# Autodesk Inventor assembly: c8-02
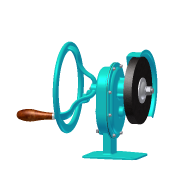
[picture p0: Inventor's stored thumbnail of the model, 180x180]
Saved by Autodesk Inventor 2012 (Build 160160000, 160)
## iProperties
Created: 2010-12
Part Number: c8-02
Document SubType Name: Assembly
Designer: Thom Tremblay
Author: Thom Tremblay
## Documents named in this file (27)
- C:\Users\VMuser\Desktop\Inventor 2012 Essentials\Assemblies\Chapter 8\c8-02.iam
- C:\Users\VMuser\Desktop\Inventor 2012 Essentials\Content Center Files\en-US\ANSI B93.98M\ANSI_B93.98M - 15x35x7-Type 2.ipt
- C:\Users\VMuser\Desktop\Inventor 2012 Essentials\Content Center Files\en-US\SKF B - angular contact\SKF B7202 BE.ipt
- C:\Users\VMuser\Desktop\Inventor 2012 Essentials\Content Center Files\en-US\IS 7483\IS 7483 - M4 x 8.ipt
- C:\Users\VMuser\Desktop\Inventor 2012 Essentials\Content Center Files\en-US\ISO 2795  F\ISO 2795 - 10 x 14 x 10F.ipt
- C:\Users\VMuser\Desktop\Inventor 2012 Essentials\Content Center Files\en-US\STN 022930\STN 022930 - 10.ipt
- C:\Users\VMuser\Desktop\Inventor 2012 Essentials\Content Center Files\en-US\STN 022930\STN 022930 - 15.ipt
- C:\Users\VMuser\Desktop\Inventor 2012 Essentials\Content Center Files\en-US\DIN 128\DIN 128 - A12.ipt
- C:\Users\VMuser\Desktop\Inventor 2012 Essentials\Content Center Files\en-US\ISO 4032\ISO 4032 - M12ISO.ipt
- C:\Users\VMuser\Desktop\Inventor 2012 Essentials\Content Center Files\en-US\ISO 4145 T8\ISO 4145 Plug T8 1_8.ipt
- C:\Users\VMuser\Desktop\Inventor 2012 Essentials\Parts\Chapter 8\c8-01.ipt
- C:\Users\VMuser\Desktop\Inventor 2012 Essentials\Parts\Chapter 8\c8-02.ipt
- C:\Users\VMuser\Desktop\Inventor 2012 Essentials\Parts\Chapter 8\c8-03.ipt
- C:\Users\VMuser\Desktop\Inventor 2012 Essentials\Parts\Chapter 8\c8-04.ipt
- C:\Users\VMuser\Desktop\Inventor 2012 Essentials\Parts\Chapter 8\c8-05.ipt
- C:\Users\VMuser\Desktop\Inventor 2012 Essentials\Parts\Chapter 8\c8-08.ipt
- C:\Users\VMuser\Desktop\Inventor 2012 Essentials\Parts\Chapter 8\c8-06.ipt
- C:\Users\VMuser\Desktop\Inventor 2012 Essentials\Parts\Chapter 8\c8-07.ipt
- C:\Users\VMuser\Desktop\Inventor 2012 Essentials\Assemblies\Chapter 8\Design Accelerators\Shaft c8-01.iam
- C:\Users\VMuser\Desktop\Inventor 2012 Essentials\Assemblies\Chapter 8\Design Accelerators\Shaft c8-02.iam
- C:\Users\VMuser\Desktop\Inventor 2012 Essentials\Assemblies\Chapter 8\Design Accelerators\Shaft c8-03.iam
- C:\Users\VMuser\Desktop\Inventor 2012 Essentials\Assemblies\Chapter 8\Design Accelerators\Cut Gear c08-01.iam
- C:\Users\VMuser\Desktop\Inventor 2012 Essentials\Assemblies\Chapter 8\Design Accelerators\Cut Gear c08-02.iam
- C:\Users\VMuser\Desktop\Inventor 2012 Essentials\Assemblies\Chapter 8\Design Accelerators\Spur Gear c98-01.iam
- C:\Users\VMuser\Desktop\Inventor 2012 Essentials\Assemblies\Chapter 8\Design Accelerators\Key Connection c8-01.iam
- C:\Users\VMuser\Desktop\Inventor 2012 Essentials\Assemblies\Chapter 8\Design Accelerators\Bolted Connection c8-01.iam
- C:\Users\VMuser\Desktop\Inventor 2012 Essentials\Assemblies\Chapter 8\Design Accelerators\Bolted Connection c8-02.iam
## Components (31 placed, 24 different names)
1. c8-01:1 — Insert:1, Flush:3, Insert:27, Insert:28, Insert:39, Angle:19
2. c8-02:1 — Insert:1, Insert:17, Insert:18, Insert:25, Insert:26, Insert:40, Angle:19, Mate:18, Mate:19
3. ANSI/B93.98M 15x35x7-Type 2:1 — Insert:40
4. c8-03:1 — Flush:3
5. c8-04:1 — Insert:10, Angle:17, Insert:49, Mate:16, Angle:20
6. c8-05:1 — Insert:10
7. c8-08:1 — Insert:13, Insert:16, Insert:48
8. c8-08:2 — Insert:13
9. c8-06:1 — Insert:16, Angle:11
10. c8-07:1 — Insert:17, Insert:18
11. SKF B- Angular contact SKF B7202 BE:1 — Insert:25, Insert:45
12. IS 7483 M4 x 8:1
13. IS 7483 M4 x 8:2
14. ISO 2795 (Flanged) 10 x 14 x 10:1 — Insert:26
15. ISO 2795 (Flanged) 10 x 14 x 10:2 — Insert:27, Insert:46
16. ISO 2795 (Flanged) 10 x 14 x 10:3 — Insert:28, Insert:41
17. STN 022930 10:1 — Angle:16
18. STN 022930 15:1
19. STN 022930 15:2
20. DIN 128 A12:1 — Angle:10
21. ISO 4032 M12:1 — Angle:10, Angle:11, Angle:18
22. ISO 4145 Plug T8 1/8:1 — Insert:39
23. Input Shaft [sub-assembly] — Insert:41, Angle:16, Angle:17, Insert:49, Mate:17, Rotation:1, Rotation:2
24. Output Shaft:2 [sub-assembly] — Insert:45, Flush:4, Insert:48, Angle:18, Rotation:2
25. Transfer Shaft:1 [sub-assembly] — Insert:46, Mate:12, Flush:5, Angle:14, Mate:13, Angle:15, Rotation:1, Rotation:3
26. Cut Gear:1 [sub-assembly]
27. Cut Gear:2 [sub-assembly]
28. Cut Gear:3 [sub-assembly] — Mate:12, Flush:4, Angle:15, Rotation:3
29. Key Connection:1 [sub-assembly] — Flush:5, Angle:14, Mate:13
30. Housing Bolts:1 [sub-assembly] — Mate:18, Mate:19
31. Wheel Bolt [sub-assembly] — Mate:16, Mate:17, Angle:20
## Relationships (38: Insert 17, Angle 9, Mate 6, Flush 3, RelateRotation 3)
- Insert:1: c8-01:1 ↔ c8-02:1
- Flush:3: c8-01:1 ↔ c8-03:1
- Insert:10: c8-04:1 ↔ c8-05:1
- Insert:13: c8-08:1 ↔ c8-08:2
- Insert:16: c8-08:1 ↔ c8-06:1
- Insert:17: c8-02:1 ↔ c8-07:1
- Insert:18: c8-02:1 ↔ c8-07:1
- Insert:25: c8-02:1 ↔ SKF B- Angular contact SKF B7202 BE:1
- Insert:26: c8-02:1 ↔ ISO 2795 (Flanged) 10 x 14 x 10:1
- Insert:27: c8-01:1 ↔ ISO 2795 (Flanged) 10 x 14 x 10:2
- Insert:28: c8-01:1 ↔ ISO 2795 (Flanged) 10 x 14 x 10:3
- Angle:10: DIN 128 A12:1 ↔ ISO 4032 M12:1
- Angle:11: c8-06:1 ↔ ISO 4032 M12:1
- Insert:39: c8-01:1 ↔ ISO 4145 Plug T8 1/8:1
- Insert:40: c8-02:1 ↔ ANSI/B93.98M 15x35x7-Type 2:1
- Insert:41: ISO 2795 (Flanged) 10 x 14 x 10:3 ↔ Input Shaft
- Insert:45: SKF B- Angular contact SKF B7202 BE:1 ↔ Output Shaft:2
- Insert:46: ISO 2795 (Flanged) 10 x 14 x 10:2 ↔ Transfer Shaft:1
- Mate:12: Transfer Shaft:1 ↔ Cut Gear:3
- Flush:4: Output Shaft:2 ↔ Cut Gear:3
- Flush:5: Transfer Shaft:1 ↔ Key Connection:1
- Angle:14: Transfer Shaft:1 ↔ Key Connection:1
- Mate:13: Transfer Shaft:1 ↔ Key Connection:1
- Angle:15: Transfer Shaft:1 ↔ Cut Gear:3
- Angle:16: STN 022930 10:1 ↔ Input Shaft
- Angle:17: c8-04:1 ↔ Input Shaft
- Insert:48: c8-08:1 ↔ Output Shaft:2
- Angle:18: ISO 4032 M12:1 ↔ Output Shaft:2
- Insert:49: c8-04:1 ↔ Input Shaft
- Mate:16: c8-04:1 ↔ Wheel Bolt
- Mate:17: Input Shaft ↔ Wheel Bolt
- Angle:19: c8-01:1 ↔ c8-02:1
- Rotation:1 [RelateRotation]: Input Shaft ↔ Transfer Shaft:1
- Rotation:2 [RelateRotation]: Input Shaft ↔ Output Shaft:2
- Rotation:3 [RelateRotation]: Transfer Shaft:1 ↔ Cut Gear:3
- Mate:18: c8-02:1 ↔ Housing Bolts:1
- Mate:19: c8-02:1 ↔ Housing Bolts:1
- Angle:20: c8-04:1 ↔ Wheel Bolt
